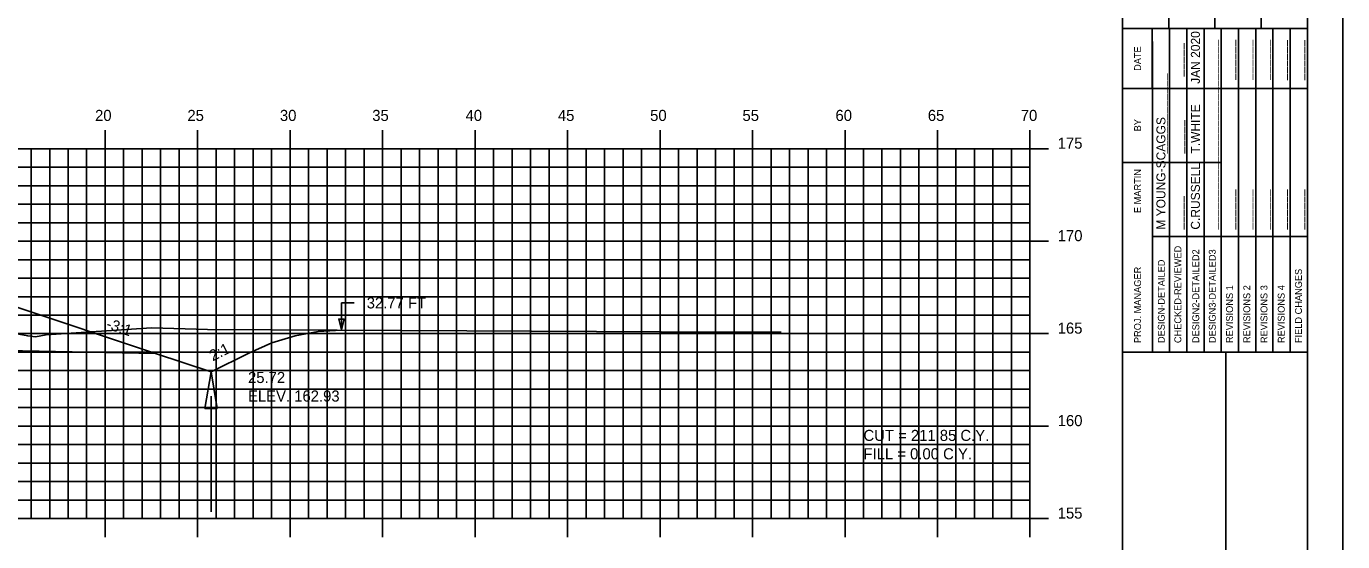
# Model space of a CAD drawing. Extents: x 1142311 to 1142481, y 608981 to 609091.
# Drawn here: x 1142410 to 1142481.2, y 609019.1 to 609047 of the extents above; entities that cross this region are included whole.
import ezdxf

# ---------------------------------------------------------------- set-up
doc = ezdxf.new("R2010")
doc.units = 0
for name, color, linetype in [('ANNOTATION', 7, 'Continuous'), ('BORDER', 7, 'Continuous'), ('D_Drainage_Ditch_Line', 7, 'Continuous'), ('D_Roadway_SlopeLines', 7, 'Continuous'), ('D_Roadway_SubGrade', 7, 'Continuous'), ('D_Text_Standard', 7, 'Continuous'), ('H_V ANNOTATION', 7, 'Continuous'), ('MAJOR', 7, 'Continuous'), ('MINOR', 7, 'Continuous'), ('PLOT BOUNDARY', 7, 'Continuous'), ('S_Roadway_Centerline', 7, 'Continuous')]:
    doc.layers.add(name, color=color, linetype=linetype)

msp = doc.modelspace()

# ---------------------------------------------------------------- linework, layer by layer
msp.add_lwpolyline([(1142360.574, 609031.058), (1142361.824, 609030.961), (1142363.074, 609030.713), (1142364.324, 609030.314), (1142365.574, 609029.765), (1142368.572, 609028.266), (1142371.572, 609029.266), (1142379.296, 609031.84), (1142379.297, 609031.84), (1142383.297, 609032), (1142394.297, 609032.22), (1142405.297, 609032), (1142409.297, 609031.84), (1142417.02, 609029.266), (1142420.02, 609028.266), (1142422.066, 609029.288), (1142423.316, 609029.835), (1142424.566, 609030.223), (1142425.816, 609030.453), (1142427.066, 609030.525)])
at = {"layer": 'BORDER'}
for p, q in [((1142469.297, 608984.335), (1142469.297, 609089.335)), ((1142471.797, 609046.838), (1142471.797, 609055.485)), ((1142474.297, 609046.838), (1142474.297, 609055.485)), ((1142476.797, 609046.838), (1142476.797, 609055.485)), ((1142469.297, 609046.838), (1142479.297, 609046.838)), ((1142469.297, 609029.338), (1142479.297, 609029.338)), ((1142474.888, 608994.338), (1142474.888, 609029.338))]:
    msp.add_line(p, q, dxfattribs=at)
msp.add_lwpolyline([(1142319.297, 608984.335), (1142479.297, 608984.335), (1142479.297, 609089.335), (1142319.297, 609089.335)], close=True, dxfattribs=at)
for points in [[(1142470.912, 609043.588), (1142470.912, 609046.838)], [(1142471.845, 609029.341), (1142471.845, 609046.838)], [(1142472.776, 609046.838), (1142472.776, 609029.341)], [(1142473.708, 609029.341), (1142473.708, 609046.838)], [(1142474.64, 609029.341), (1142474.64, 609046.838)], [(1142475.571, 609029.341), (1142475.571, 609046.838)], [(1142476.503, 609029.341), (1142476.503, 609046.838)], [(1142477.435, 609029.341), (1142477.435, 609046.838)], [(1142478.366, 609029.341), (1142478.366, 609046.838)], [(1142470.913, 609029.341), (1142470.913, 609046.132)], [(1142469.297, 609043.588), (1142479.297, 609043.588)], [(1142469.297, 609039.588), (1142470.913, 609039.588)], [(1142470.912, 609039.588), (1142474.639, 609039.588)], [(1142470.912, 609035.588), (1142479.297, 609035.588)]]:
    msp.add_lwpolyline(points, dxfattribs=at)
at = {"layer": 'D_Drainage_Ditch_Line'}
msp.add_line((1142420.02, 609026.954), (1142420.02, 609020.71), dxfattribs=at)
msp.add_lwpolyline([(1142420.348, 609026.297), (1142419.692, 609026.297), (1142420.02, 609028.266)], close=True, dxfattribs=at)
at = {"layer": 'D_Roadway_SlopeLines'}
for points in [[(1142420.02, 609028.266), (1142422.066, 609029.288), (1142423.316, 609029.835), (1142424.566, 609030.223), (1142425.816, 609030.453), (1142427.066, 609030.525)], [(1142417.02, 609029.266), (1142420.02, 609028.266)]]:
    msp.add_lwpolyline(points, dxfattribs=at)
at = {"layer": 'D_Roadway_SubGrade'}
msp.add_lwpolyline([(1142405.297, 609031.584), (1142405.297, 609031.75), (1142409.297, 609031.59), (1142409.297, 609031.84), (1142409.297, 609031.84), (1142417.02, 609029.266), (1142405.297, 609029.5)], close=True, dxfattribs=at)
at = {"layer": 'D_Text_Standard'}
msp.add_lwpolyline([(1142427.066, 609030.538), (1142427.077, 609031.998), (1142427.757, 609031.998)], dxfattribs=at)
msp.add_lwpolyline([(1142427.066, 609030.538), (1142426.925, 609031.122), (1142427.216, 609031.119)], close=True, dxfattribs=at)
at = {"layer": 'MAJOR'}
for p, q in [((1142414.297, 609041.337), (1142414.297, 609040.335)), ((1142419.297, 609041.337), (1142419.297, 609040.335)), ((1142424.297, 609041.337), (1142424.297, 609040.335)), ((1142429.297, 609041.337), (1142429.297, 609040.335)), ((1142434.297, 609041.337), (1142434.297, 609040.335)), ((1142439.297, 609041.337), (1142439.297, 609040.335)), ((1142444.297, 609041.337), (1142444.297, 609040.335)), ((1142449.297, 609041.337), (1142449.297, 609040.335)), ((1142454.297, 609041.337), (1142454.297, 609040.335)), ((1142459.297, 609041.337), (1142459.297, 609040.335)), ((1142464.297, 609041.337), (1142464.297, 609040.335)), ((1142324.297, 609040.335), (1142464.297, 609040.335)), ((1142324.297, 609040.335), (1142464.297, 609040.335)), ((1142414.297, 609020.335), (1142414.297, 609040.335)), ((1142419.297, 609020.335), (1142419.297, 609040.335)), ((1142424.297, 609020.335), (1142424.297, 609040.335)), ((1142429.297, 609020.335), (1142429.297, 609040.335)), ((1142434.297, 609020.335), (1142434.297, 609040.335)), ((1142439.297, 609020.335), (1142439.297, 609040.335)), ((1142444.297, 609020.335), (1142444.297, 609040.335)), ((1142449.297, 609020.335), (1142449.297, 609040.335)), ((1142454.297, 609020.335), (1142454.297, 609040.335)), ((1142459.297, 609020.335), (1142459.297, 609040.335)), ((1142465.299, 609040.335), (1142463.295, 609040.335)), ((1142464.297, 609020.335), (1142464.297, 609040.335)), ((1142464.297, 609020.335), (1142464.297, 609040.335)), ((1142324.297, 609035.335), (1142464.297, 609035.335)), ((1142465.299, 609035.335), (1142463.295, 609035.335)), ((1142324.297, 609030.335), (1142464.297, 609030.335)), ((1142465.299, 609030.335), (1142463.295, 609030.335)), ((1142324.297, 609025.335), (1142464.297, 609025.335)), ((1142465.299, 609025.335), (1142463.295, 609025.335)), ((1142324.297, 609020.335), (1142464.297, 609020.335)), ((1142324.297, 609020.335), (1142464.297, 609020.335)), ((1142414.297, 609019.333), (1142414.297, 609020.335)), ((1142419.297, 609019.333), (1142419.297, 609020.335)), ((1142424.297, 609019.333), (1142424.297, 609020.335)), ((1142429.297, 609019.333), (1142429.297, 609020.335)), ((1142434.297, 609019.333), (1142434.297, 609020.335)), ((1142439.297, 609019.333), (1142439.297, 609020.335)), ((1142444.297, 609019.333), (1142444.297, 609020.335)), ((1142449.297, 609019.333), (1142449.297, 609020.335)), ((1142454.297, 609019.333), (1142454.297, 609020.335)), ((1142459.297, 609019.333), (1142459.297, 609020.335)), ((1142465.299, 609020.335), (1142463.295, 609020.335)), ((1142464.297, 609019.333), (1142464.297, 609020.335))]:
    msp.add_line(p, q, dxfattribs=at)
at = {"layer": 'MINOR'}
for p, q in [((1142410.297, 609020.335), (1142410.297, 609040.335)), ((1142411.297, 609020.335), (1142411.297, 609040.335)), ((1142412.297, 609020.335), (1142412.297, 609040.335)), ((1142413.297, 609020.335), (1142413.297, 609040.335)), ((1142415.297, 609020.335), (1142415.297, 609040.335)), ((1142416.297, 609020.335), (1142416.297, 609040.335)), ((1142417.297, 609020.335), (1142417.297, 609040.335)), ((1142418.297, 609020.335), (1142418.297, 609040.335)), ((1142420.297, 609020.335), (1142420.297, 609040.335)), ((1142421.297, 609020.335), (1142421.297, 609040.335)), ((1142422.297, 609020.335), (1142422.297, 609040.335)), ((1142423.297, 609020.335), (1142423.297, 609040.335)), ((1142425.297, 609020.335), (1142425.297, 609040.335)), ((1142426.297, 609020.335), (1142426.297, 609040.335)), ((1142427.297, 609020.335), (1142427.297, 609040.335)), ((1142428.297, 609020.335), (1142428.297, 609040.335)), ((1142430.297, 609020.335), (1142430.297, 609040.335)), ((1142431.297, 609020.335), (1142431.297, 609040.335)), ((1142432.297, 609020.335), (1142432.297, 609040.335)), ((1142433.297, 609020.335), (1142433.297, 609040.335)), ((1142435.297, 609020.335), (1142435.297, 609040.335)), ((1142436.297, 609020.335), (1142436.297, 609040.335)), ((1142437.297, 609020.335), (1142437.297, 609040.335)), ((1142438.297, 609020.335), (1142438.297, 609040.335)), ((1142440.297, 609020.335), (1142440.297, 609040.335)), ((1142441.297, 609020.335), (1142441.297, 609040.335)), ((1142442.297, 609020.335), (1142442.297, 609040.335)), ((1142443.297, 609020.335), (1142443.297, 609040.335)), ((1142445.297, 609020.335), (1142445.297, 609040.335)), ((1142446.297, 609020.335), (1142446.297, 609040.335)), ((1142447.297, 609020.335), (1142447.297, 609040.335)), ((1142448.297, 609020.335), (1142448.297, 609040.335)), ((1142450.297, 609020.335), (1142450.297, 609040.335)), ((1142451.297, 609020.335), (1142451.297, 609040.335)), ((1142452.297, 609020.335), (1142452.297, 609040.335)), ((1142453.297, 609020.335), (1142453.297, 609040.335)), ((1142455.297, 609020.335), (1142455.297, 609040.335)), ((1142456.297, 609020.335), (1142456.297, 609040.335)), ((1142457.297, 609020.335), (1142457.297, 609040.335)), ((1142458.297, 609020.335), (1142458.297, 609040.335)), ((1142460.297, 609020.335), (1142460.297, 609040.335)), ((1142461.297, 609020.335), (1142461.297, 609040.335)), ((1142462.297, 609020.335), (1142462.297, 609040.335)), ((1142463.297, 609020.335), (1142463.297, 609040.335)), ((1142324.297, 609039.335), (1142464.297, 609039.335)), ((1142464.297, 609039.335), (1142463.295, 609039.335)), ((1142324.297, 609038.335), (1142464.297, 609038.335)), ((1142464.297, 609038.335), (1142463.295, 609038.335)), ((1142324.297, 609037.335), (1142464.297, 609037.335)), ((1142464.297, 609037.335), (1142463.295, 609037.335)), ((1142324.297, 609036.335), (1142464.297, 609036.335)), ((1142464.297, 609036.335), (1142463.295, 609036.335)), ((1142324.297, 609034.335), (1142464.297, 609034.335)), ((1142464.297, 609034.335), (1142463.295, 609034.335)), ((1142324.297, 609033.335), (1142464.297, 609033.335)), ((1142464.297, 609033.335), (1142463.295, 609033.335)), ((1142324.297, 609032.335), (1142464.297, 609032.335)), ((1142464.297, 609032.335), (1142463.295, 609032.335)), ((1142324.297, 609031.335), (1142464.297, 609031.335)), ((1142464.297, 609031.335), (1142463.295, 609031.335)), ((1142324.297, 609029.335), (1142464.297, 609029.335)), ((1142464.297, 609029.335), (1142463.295, 609029.335)), ((1142324.297, 609028.335), (1142464.297, 609028.335)), ((1142464.297, 609028.335), (1142463.295, 609028.335)), ((1142324.297, 609027.335), (1142464.297, 609027.335)), ((1142464.297, 609027.335), (1142463.295, 609027.335)), ((1142324.297, 609026.335), (1142464.297, 609026.335)), ((1142464.297, 609026.335), (1142463.295, 609026.335)), ((1142324.297, 609024.335), (1142464.297, 609024.335)), ((1142464.297, 609024.335), (1142463.295, 609024.335)), ((1142324.297, 609023.335), (1142464.297, 609023.335)), ((1142464.297, 609023.335), (1142463.295, 609023.335)), ((1142324.297, 609022.335), (1142464.297, 609022.335)), ((1142464.297, 609022.335), (1142463.295, 609022.335)), ((1142324.297, 609021.335), (1142464.297, 609021.335)), ((1142464.297, 609021.335), (1142463.295, 609021.335))]:
    msp.add_line(p, q, dxfattribs=at)
at = {"layer": 'PLOT BOUNDARY'}
msp.add_lwpolyline([(1142311.204, 608981.276), (1142481.204, 608981.276), (1142481.204, 609091.276), (1142311.204, 609091.276)], close=True, dxfattribs=at)
at = {"layer": 'S_Roadway_Centerline'}
msp.add_lwpolyline([(1142324.297, 609031.45), (1142339.038, 609031.267), (1142344.584, 609031.334), (1142365.956, 609030.965), (1142367.521, 609030.805), (1142367.992, 609030.755), (1142371.922, 609030.416), (1142372.533, 609030.575), (1142376.384, 609031.552), (1142376.966, 609031.616), (1142379.377, 609031.848), (1142381.17, 609031.866), (1142390.341, 609031.991), (1142392.202, 609031.893), (1142401.531, 609031.422), (1142402.162, 609031.372), (1142406.958, 609030.794), (1142410.108, 609030.213), (1142410.523, 609030.158), (1142411.1, 609030.269), (1142416.795, 609030.647), (1142419.825, 609030.564), (1142444.36, 609030.432), (1142450.84, 609030.42)], dxfattribs=at)

# ---------------------------------------------------------------- texts
at = {"layer": 'ANNOTATION'}
for s, rotation, p in [('-3:1', 341.56521, (1142414.308, 609030.624)), ('2:1', 26.56505, (1142420.116, 609028.832))]:
    msp.add_text(s, height=0.6, rotation=rotation, dxfattribs=at).set_placement(p)
at = {"layer": 'BORDER'}
for s, height, p in [('JAN 2020', 0.4845, (1142473.483, 609043.843)), ('DATE', 0.3714, (1142470.301, 609044.544)), ('_____', 0.4845, (1142472.514, 609044.243)), ('______', 0.4845, (1142474.378, 609044.063)), ('______', 0.4845, (1142475.309, 609044.065)), ('______', 0.4845, (1142476.241, 609044.067)), ('______', 0.4845, (1142477.173, 609044.067)), ('______', 0.4845, (1142478.105, 609044.036)), ('______', 0.4845, (1142479.036, 609044.036)), ('____________', 0.48455, (1142471.62, 609040.073)), ('____________', 0.48455, (1142474.378, 609040.073)), ('T.WHITE', 0.4845, (1142473.483, 609040.073)), ('M YOUNG-SCAGGS', 0.48455, (1142471.62, 609035.961)), ('BY', 0.3714, (1142470.301, 609041.273)), ('_____', 0.4845, (1142472.552, 609040.073)), ('____________', 0.48455, (1142474.378, 609035.961)), ('E MARTIN', 0.3727, (1142470.301, 609036.855)), ('C.RUSSELL', 0.4845, (1142473.483, 609035.961)), ('_____', 0.4845, (1142472.514, 609035.961)), ('______', 0.4845, (1142475.309, 609035.961)), ('______', 0.4845, (1142476.241, 609035.961)), ('______', 0.4845, (1142477.173, 609035.961)), ('______', 0.4845, (1142478.105, 609035.961)), ('______', 0.4845, (1142479.036, 609035.961)), ('CHECKED-REVIEWED', 0.37275, (1142472.478, 609029.826)), ('DESIGN3-DETAILED3', 0.37275, (1142474.341, 609029.826)), ('DESIGN-DETAILED', 0.37275, (1142471.584, 609029.826)), ('DESIGN2-DETAILED2', 0.37275, (1142473.447, 609029.826)), ('PROJ. MANAGER', 0.37275, (1142470.301, 609029.826)), ('FIELD CHANGES', 0.37275, (1142479, 609029.826)), ('REVISIONS 1', 0.37275, (1142475.273, 609029.826)), ('REVISIONS 2', 0.37275, (1142476.205, 609029.826)), ('REVISIONS 3', 0.37275, (1142477.136, 609029.826)), ('REVISIONS 4', 0.37275, (1142478.068, 609029.826))]:
    msp.add_text(s, height=height, rotation=90, dxfattribs=at).set_placement(p)
at = {"layer": 'D_Text_Standard'}
for s, p in [('32.77 FT', (1142428.437, 609031.698)), ('25.72', (1142422.02, 609027.666)), ('ELEV. 162.93', (1142422.02, 609026.664)), ('CUT = 211.85 C.Y.', (1142455.297, 609024.535)), ('FILL = 0.00 C.Y.', (1142455.297, 609023.539))]:
    msp.add_text(s, height=0.6, dxfattribs=at).set_placement(p)
at = {"layer": 'H_V ANNOTATION'}
for s, p in [('20', (1142413.751, 609041.835)), ('25', (1142418.743, 609041.835)), ('30', (1142423.746, 609041.835)), ('35', (1142428.738, 609041.835)), ('40', (1142433.783, 609041.835)), ('45', (1142438.775, 609041.835)), ('50', (1142443.762, 609041.835)), ('55', (1142448.754, 609041.835)), ('60', (1142453.783, 609041.835)), ('65', (1142458.775, 609041.835)), ('70', (1142463.799, 609041.835)), ('175', (1142465.797, 609040.335)), ('170', (1142465.797, 609035.335)), ('165', (1142465.797, 609030.335)), ('160', (1142465.797, 609025.335)), ('155', (1142465.797, 609020.335))]:
    msp.add_text(s, height=0.6, dxfattribs=at).set_placement(p)

doc.saveas('drawing.dxf')
